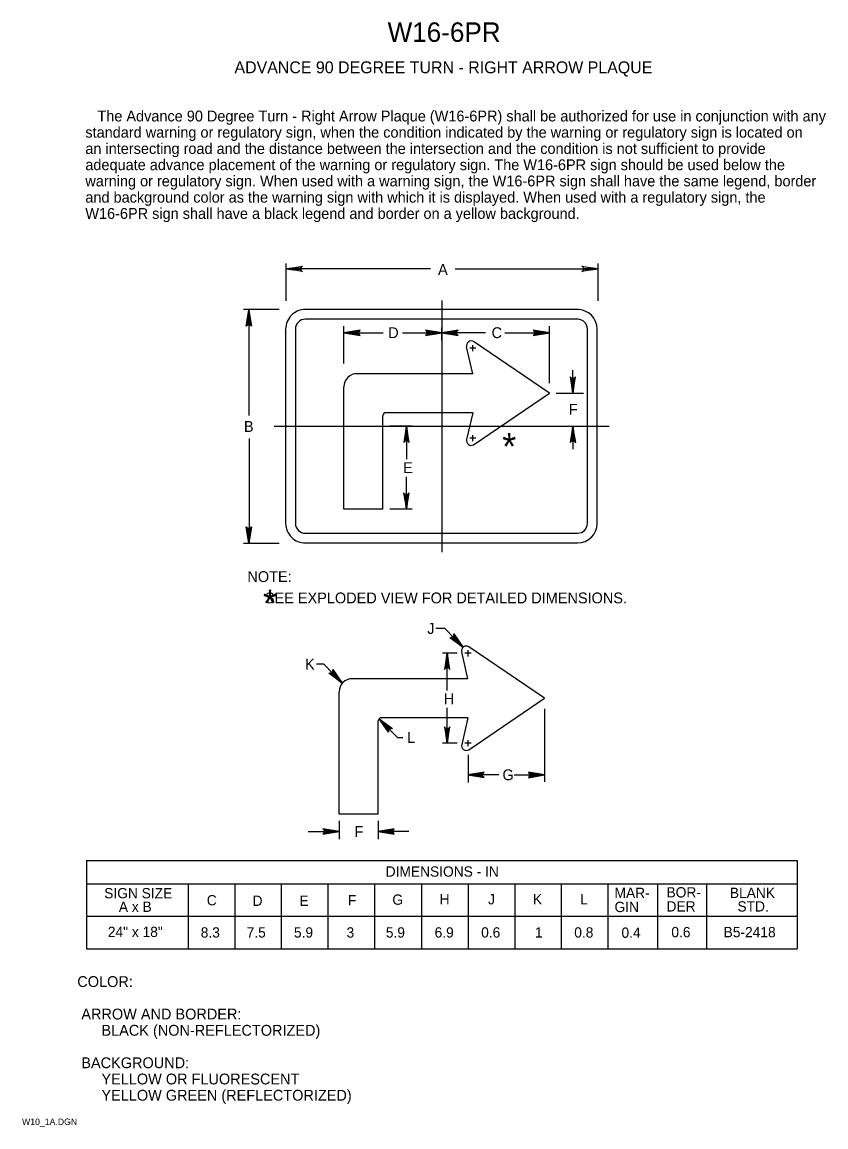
# Model space of a CAD drawing. Extents: x 0.013 to 0.198, y 0.004 to 0.259.
import ezdxf

# ---------------------------------------------------------------- set-up
doc = ezdxf.new("R2010")
doc.units = 0
for name, color, linetype in [('1', 7, 'Continuous'), ('2', 7, 'Continuous'), ('3', 7, 'Continuous')]:
    doc.layers.add(name, color=color, linetype=linetype)

# ---------------------------------------------------------------- blocks, each defined once
blk = doc.blocks.new('RARROW')
at = {"layer": '3'}
for p, q in [((-2.156, 0.28500000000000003), (-2.2665, 0.384625)), ((-2.2665, 0.384625), (0, 0)), ((0, 0), (-2.2665, -0.379125)), ((-2.156, 0.28500000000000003), (-2.075625, 0.12075)), ((0, 0), (-2.156, 0.28500000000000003)), ((-2.14975, -0.2705), (0, 0)), ((-2.075625, 0.12075), (0, 0)), ((0, 0), (-2.074, -0.108)), ((-2.2665, -0.379125), (-2.14975, -0.2705)), ((-2.074, -0.108), (-2.14975, -0.2705))]:
    blk.add_line(p, q, dxfattribs=at)

msp = doc.modelspace()

# ---------------------------------------------------------------- linework, layer by layer
at = {"layer": '1'}
for p, q in [((0.10950949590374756, 0.19475368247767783), (0.10950949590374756, 0.13669624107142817)), ((0.11666823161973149, 0.17787309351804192), (0.08993050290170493, 0.17787309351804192)), ((0.1166682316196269, 0.16887309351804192), (0.09667553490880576, 0.16887309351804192)), ((0.07079216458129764, 0.16574452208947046), (0.14811133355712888, 0.16574452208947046)), ((0.09593050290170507, 0.1466010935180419), (0.08693050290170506, 0.14660109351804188)), ((0.11554471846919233, 0.10743259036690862), (0.08880698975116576, 0.10743259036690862)), ((0.11554471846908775, 0.09843259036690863), (0.09555202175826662, 0.09843259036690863)), ((0.09480698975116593, 0.07616059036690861), (0.08580698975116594, 0.07616059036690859))]:
    msp.add_line(p, q, dxfattribs=at)
for centre, radius, start, end in [((0.08993050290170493, 0.1748730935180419), 0.0029999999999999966, 89.50813388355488, 180), ((0.09668050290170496, 0.16812309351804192), 0.0007499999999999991, 90.19273955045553, 90.19273955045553), ((0.09668050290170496, 0.16812309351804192), 0.0007499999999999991, 90.3795294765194, 179.99999999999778), ((0.09668050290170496, 0.16812309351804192), 0.0007499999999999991, 90.25516062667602, 90.25565038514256), ((0.08880698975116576, 0.1044325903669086), 0.0029999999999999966, 89.50813388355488, 180), ((0.09555698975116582, 0.09768259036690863), 0.0007499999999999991, 90.19273955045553, 90.19273955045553), ((0.09555698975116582, 0.09768259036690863), 0.0007499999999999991, 90.3795294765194, 179.99999999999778), ((0.09555698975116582, 0.09768259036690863), 0.0007499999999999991, 90.25516062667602, 90.25565038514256)]:
    msp.add_arc(centre, radius, start, end, dxfattribs=at)
at = {"layer": '3'}
for p, q in [((0.07359843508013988, 0.1946907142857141), (0.07359843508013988, 0.20331284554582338)), ((0.10689328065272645, 0.20206284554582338), (0.07363359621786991, 0.20206284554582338)), ((0.1125947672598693, 0.20206284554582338), (0.1455984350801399, 0.20206284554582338)), ((0.1455984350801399, 0.1946907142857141), (0.1455984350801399, 0.20331284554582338)), ((0.07196701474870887, 0.19268784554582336), (0.0637585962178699, 0.19268784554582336)), ((0.0650085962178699, 0.1682504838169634), (0.0650085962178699, 0.19268784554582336)), ((0.14105197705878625, 0.1926907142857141), (0.07796701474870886, 0.1926907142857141)), ((0.14099731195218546, 0.1904407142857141), (0.07796701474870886, 0.1904407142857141)), ((0.08693050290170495, 0.18023608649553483), (0.08693050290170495, 0.1888582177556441)), ((0.13436436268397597, 0.1756636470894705), (0.13436436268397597, 0.1888582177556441)), ((0.07346701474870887, 0.1881907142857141), (0.07346701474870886, 0.14329059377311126)), ((0.07571701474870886, 0.1881907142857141), (0.07571701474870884, 0.14329059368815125)), ((0.08693050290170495, 0.18730692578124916), (0.09596335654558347, 0.18730692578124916)), ((0.10046977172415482, 0.18730692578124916), (0.109505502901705, 0.18730692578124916)), ((0.11961581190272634, 0.18730692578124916), (0.109505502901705, 0.18730692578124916)), ((0.10950749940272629, 0.1855104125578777), (0.10950749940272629, 0.18854687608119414)), ((0.12402263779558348, 0.18730692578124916), (0.13436436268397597, 0.18730692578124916)), ((0.14311543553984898, 0.14329446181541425), (0.14311543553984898, 0.18819458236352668)), ((0.14536543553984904, 0.14329446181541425), (0.145365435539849, 0.18819458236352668)), ((0.11666823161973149, 0.17787309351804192), (0.11523606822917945, 0.1840800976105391)), ((0.11668104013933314, 0.18376059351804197), (0.11596392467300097, 0.18376059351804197)), ((0.11668104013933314, 0.18376059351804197), (0.11668104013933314, 0.1844777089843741)), ((0.11668104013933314, 0.18304347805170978), (0.11668104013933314, 0.18376059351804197)), ((0.1173981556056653, 0.18376059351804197), (0.11668104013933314, 0.18376059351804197)), ((0.13436436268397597, 0.17337309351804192), (0.11685011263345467, 0.1852776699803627)), ((0.13975559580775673, 0.17340306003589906), (0.13975559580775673, 0.17872373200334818)), ((0.08693050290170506, 0.14660109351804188), (0.08693050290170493, 0.1748730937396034)), ((0.11684707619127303, 0.16145791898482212), (0.13436436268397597, 0.17337309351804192)), ((0.13592554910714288, 0.17337309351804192), (0.14222058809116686, 0.17337309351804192)), ((0.1166682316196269, 0.16887309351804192), (0.11523606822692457, 0.16266608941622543)), ((0.09593050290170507, 0.1466010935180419), (0.09593050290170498, 0.16812309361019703)), ((0.10265277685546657, 0.16574452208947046), (0.0974990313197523, 0.16574452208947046)), ((0.10135723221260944, 0.1657383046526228), (0.10135723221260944, 0.1581697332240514)), ((0.11668104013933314, 0.16298559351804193), (0.11668104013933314, 0.1637027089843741)), ((0.13592554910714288, 0.16574678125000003), (0.14222058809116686, 0.16574678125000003)), ((0.1397789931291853, 0.1657383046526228), (0.1397789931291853, 0.16044909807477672)), ((0.0650085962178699, 0.1629473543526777), (0.0650085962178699, 0.13885684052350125)), ((0.11668104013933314, 0.16298559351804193), (0.11596392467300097, 0.16298559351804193)), ((0.11668104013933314, 0.1622684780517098), (0.11668104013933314, 0.16298559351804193)), ((0.1173981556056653, 0.16298559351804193), (0.11668104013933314, 0.16298559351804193)), ((0.10133383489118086, 0.1466010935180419), (0.10133383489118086, 0.15407830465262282)), ((0.102629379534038, 0.1466010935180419), (0.09747563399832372, 0.1466010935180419)), ((0.07796701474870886, 0.1410405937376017), (0.14086543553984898, 0.1410405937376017)), ((0.07196701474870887, 0.13868784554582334), (0.0637585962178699, 0.13868784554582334)), ((0.07796701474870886, 0.1387905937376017), (0.14086543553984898, 0.1387905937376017)), ((0.11018019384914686, 0.11901097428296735), (0.10811614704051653, 0.11901097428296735)), ((0.11443908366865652, 0.1146778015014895), (0.11018019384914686, 0.11901097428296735)), ((0.13324084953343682, 0.10293259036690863), (0.11572659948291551, 0.11483716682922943)), ((0.11308116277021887, 0.11332009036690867), (0.10963910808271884, 0.11332009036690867)), ((0.11076471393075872, 0.10473138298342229), (0.11076471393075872, 0.11251084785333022)), ((0.11554471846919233, 0.10743259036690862), (0.11411255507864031, 0.11363959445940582)), ((0.115557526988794, 0.11332009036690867), (0.11484041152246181, 0.11332009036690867)), ((0.115557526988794, 0.11332009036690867), (0.115557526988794, 0.11403720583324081)), ((0.11627464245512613, 0.11332009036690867), (0.115557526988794, 0.11332009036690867)), ((0.115557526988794, 0.11260297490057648), (0.115557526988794, 0.11332009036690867)), ((0.08228011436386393, 0.11078240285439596), (0.08060757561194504, 0.11078240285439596)), ((0.08653900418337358, 0.1064492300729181), (0.08228011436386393, 0.11078240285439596)), ((0.08580698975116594, 0.07616059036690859), (0.08580698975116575, 0.10443259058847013)), ((0.11572356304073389, 0.09101741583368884), (0.13324084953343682, 0.10293259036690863)), ((0.11076471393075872, 0.0925565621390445), (0.11076471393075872, 0.10068566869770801)), ((0.13324084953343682, 0.10050852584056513), (0.13324084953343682, 0.08358852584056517)), ((0.09480698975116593, 0.07616059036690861), (0.09480698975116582, 0.09768259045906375)), ((0.09501900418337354, 0.09819780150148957), (0.09927789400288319, 0.09386462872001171)), ((0.11554471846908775, 0.09843259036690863), (0.11411255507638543, 0.09222558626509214)), ((0.09927789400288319, 0.09386462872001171), (0.10051614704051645, 0.09386462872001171)), ((0.11308194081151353, 0.09254509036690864), (0.10963988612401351, 0.09254509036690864)), ((0.115557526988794, 0.09254509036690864), (0.11484041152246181, 0.09254509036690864)), ((0.115557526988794, 0.09254509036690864), (0.115557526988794, 0.09326220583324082)), ((0.115557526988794, 0.09182797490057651), (0.115557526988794, 0.09254509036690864)), ((0.11627464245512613, 0.09254509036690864), (0.115557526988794, 0.09254509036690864)), ((0.115557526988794, 0.08985138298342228), (0.115557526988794, 0.0834513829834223)), ((0.12266765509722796, 0.08521709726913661), (0.11552765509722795, 0.08521709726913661)), ((0.12622194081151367, 0.08521709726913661), (0.13324084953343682, 0.08521709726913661)), ((0.08580698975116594, 0.07465494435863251), (0.08580698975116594, 0.07041494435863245)), ((0.09480698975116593, 0.07465494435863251), (0.09480698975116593, 0.07041494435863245)), ((0.07866698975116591, 0.07218065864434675), (0.08580698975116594, 0.07218065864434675)), ((0.10193043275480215, 0.07218065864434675), (0.09479043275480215, 0.07218065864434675)), ((0.027461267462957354, 0.0654753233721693), (0.19155772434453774, 0.0654753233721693)), ((0.027461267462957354, 0.0654753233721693), (0.027461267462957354, 0.04510032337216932)), ((0.19155772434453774, 0.06547532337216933), (0.19155772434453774, 0.04510032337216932)), ((0.027461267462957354, 0.06010032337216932), (0.19155772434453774, 0.06010032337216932)), ((0.05096126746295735, 0.06010032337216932), (0.05096126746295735, 0.04510032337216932)), ((0.06171126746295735, 0.06010032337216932), (0.06171126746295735, 0.04510032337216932)), ((0.07246126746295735, 0.06010032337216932), (0.07246126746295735, 0.04510032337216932)), ((0.08321126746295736, 0.06010032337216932), (0.08321126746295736, 0.04510032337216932)), ((0.09396126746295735, 0.06010032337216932), (0.09396126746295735, 0.04510032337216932)), ((0.10483626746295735, 0.06010032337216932), (0.10483626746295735, 0.04510032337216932)), ((0.11558626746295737, 0.06010032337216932), (0.11558626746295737, 0.04510032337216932)), ((0.12633626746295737, 0.06010032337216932), (0.12633626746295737, 0.04510032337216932)), ((0.13708626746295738, 0.06010032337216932), (0.13708626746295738, 0.04510032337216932)), ((0.1478362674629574, 0.06010032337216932), (0.1478362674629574, 0.04510032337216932)), ((0.1592891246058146, 0.06010032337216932), (0.1592891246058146, 0.04510032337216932)), ((0.17062169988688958, 0.06010032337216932), (0.17062169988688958, 0.04510032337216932)), ((0.027461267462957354, 0.05260032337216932), (0.19155772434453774, 0.05260032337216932)), ((0.027461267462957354, 0.04510032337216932), (0.19155772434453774, 0.04510032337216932))]:
    msp.add_line(p, q, dxfattribs=at)
for centre, radius, start, end in [((0.07799927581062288, 0.1881623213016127), 0.004532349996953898, 89.64106666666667, 179.6410666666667), ((0.14086543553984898, 0.18819458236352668), 0.0045000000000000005, 0, 90), ((0.07799927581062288, 0.1881623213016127), 0.0022824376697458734, 89.28723611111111, 179.2872361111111), ((0.14086543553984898, 0.18819458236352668), 0.0022500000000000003, 0, 90), ((0.11629692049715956, 0.18433678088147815), 0.0010914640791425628, 59.54676398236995, 193.60184176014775), ((0.11629692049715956, 0.16240940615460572), 0.0010914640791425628, 166.39815823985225, 300.45323601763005), ((0.07799540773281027, 0.1433228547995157), 0.004528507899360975, 180.4081777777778, 270.40817777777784), ((0.07799540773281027, 0.1433228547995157), 0.002278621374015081, 180.81123055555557, 270.81123055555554), ((0.14086543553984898, 0.14329446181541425), 0.0045000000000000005, 270, 0), ((0.14086543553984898, 0.14329446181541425), 0.0022500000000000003, 270, 0), ((0.11517340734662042, 0.11389627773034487), 0.0010914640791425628, 59.54676398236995, 193.60184176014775), ((0.11517340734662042, 0.09196890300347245), 0.0010914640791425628, 166.39815823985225, 300.45323601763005)]:
    msp.add_arc(centre, radius, start, end, dxfattribs=at)

# ---------------------------------------------------------------- block references
for p, xscale, yscale, rotation in [((0.07359201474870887, 0.2020657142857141), 0.0016545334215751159, 0.0016366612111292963, 180), ((0.06496701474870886, 0.19256571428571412), 0.0016545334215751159, 0.0016366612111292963, 90), ((0.08693050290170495, 0.18730692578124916), 0.0016545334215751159, -0.0016366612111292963, 180), ((0.109505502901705, 0.18730692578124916), 0.0016545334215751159, -0.0016366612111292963, 180), ((0.13975559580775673, 0.17340306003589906), 0.0016545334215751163, -0.0016366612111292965, -89.99999999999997), ((0.10135723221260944, 0.1657383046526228), 0.0016545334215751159, -0.0016366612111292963, 90.00000000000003), ((0.1397789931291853, 0.1657383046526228), 0.0016545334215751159, -0.0016366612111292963, 90.00000000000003), ((0.10133383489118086, 0.1466010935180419), 0.0016545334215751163, -0.0016366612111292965, -89.99999999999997), ((0.06496701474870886, 0.13873470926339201), 0.0016545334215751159, 0.0016366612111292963, -90), ((0.11443908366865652, 0.1146778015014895), 0.0016545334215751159, 0.0016366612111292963, -45.49534021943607), ((0.11075051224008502, 0.11334852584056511), 0.0016545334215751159, -0.0016366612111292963, 90.00000000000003), ((0.08653900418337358, 0.1064492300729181), 0.0016545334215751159, 0.0016366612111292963, -45.49534021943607), ((0.09501900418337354, 0.09819780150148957), 0.0016545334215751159, 0.0016366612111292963, 134.5046597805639), ((0.11076471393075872, 0.0925565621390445), 0.0016545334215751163, -0.0016366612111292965, -89.99999999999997), ((0.11552765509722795, 0.08521709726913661), 0.0016545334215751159, -0.0016366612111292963, 180), ((0.09479043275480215, 0.07218065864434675), 0.0016545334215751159, -0.0016366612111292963, 180)]:
    msp.add_blockref('RARROW', p, dxfattribs=dict(at, xscale=xscale, yscale=yscale, rotation=rotation))
at = {"layer": '3', "xscale": 0.0016545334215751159}
for p, yscale in [((0.1455984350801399, 0.20206284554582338), 0.0016366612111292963), ((0.109505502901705, 0.18730692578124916), -0.0016366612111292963), ((0.13436436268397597, 0.18730692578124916), -0.0016366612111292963), ((0.13324084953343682, 0.08521709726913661), -0.0016366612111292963), ((0.08580698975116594, 0.07218065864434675), -0.0016366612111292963)]:
    msp.add_blockref('RARROW', p, dxfattribs=dict(at, yscale=yscale))

# ---------------------------------------------------------------- texts
at = {"layer": '1'}
for s, height, p in [('W16-6PR', 0.0045000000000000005, (0.09699590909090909, 0.2545)), ('ADVANCE 90 DEGREE TURN - RIGHT ARROW PLAQUE', 0.00275025, (0.06165046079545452, 0.24725)), ('*', 0.006220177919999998, (0.12344607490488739, 0.15797148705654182)), ('*', 0.006220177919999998, (0.068223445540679, 0.12174596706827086)), ('COLOR:', 0.0024997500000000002, (0.025375, 0.036249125)), (' ARROW AND BORDER:', 0.0024997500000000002, (0.025375, 0.028749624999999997)), ('      BLACK (NON-REFLECTORIZED)', 0.0024997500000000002, (0.025375, 0.024999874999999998)), (' BACKGROUND:', 0.0024997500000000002, (0.025375, 0.017500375)), ('      YELLOW OR FLUORESCENT ', 0.0024997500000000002, (0.025375, 0.013750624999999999)), ('      YELLOW GREEN (REFLECTORIZED)', 0.0024997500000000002, (0.025375, 0.010000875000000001)), ('W10_1A.DGN', 0.0015, (0.012625, 0.004375))]:
    msp.add_text(s, height=height, dxfattribs=at).set_placement(p)
at = {"layer": '2'}
for s, p in [('   The Advance 90 Degree Turn - Right Arrow Plaque (W16-6PR) shall be authorized for use in conjunction with any ', (0.027230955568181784, 0.23612525)), ('standard warning or regulatory sign, when the condition indicated by the warning or regulatory sign is located on ', (0.027230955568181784, 0.23237549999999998)), ('an intersecting road and the distance between the intersection and the condition is not sufficient to provide ', (0.027230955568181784, 0.22862575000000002)), ('adequate advance placement of the warning or regulatory sign. The W16-6PR sign should be used below the ', (0.027230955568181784, 0.22487600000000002)), ('warning or regulatory sign. When used with a warning sign, the W16-6PR sign shall have the same legend, border ', (0.027230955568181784, 0.22112625)), ('and background color as the warning sign with which it is displayed. When used with a regulatory sign, the ', (0.027230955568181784, 0.2173765)), ('W16-6PR sign shall have a black legend and border on a yellow background.', (0.027230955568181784, 0.21362675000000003))]:
    msp.add_text(s, height=0.0024997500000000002, dxfattribs=at).set_placement(p)
at = {"layer": '3'}
for s, height, p in [('A', 0.0024997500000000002, (0.10864247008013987, 0.2006907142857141)), ('D', 0.0024997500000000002, (0.09713705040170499, 0.18609318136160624)), ('C', 0.0024997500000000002, (0.12099814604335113, 0.18609318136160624)), ('B', 0.0024997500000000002, (0.06384201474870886, 0.16443797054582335)), ('E', 0.0024997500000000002, (0.10058327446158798, 0.15492293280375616)), ('NOTE:', 0.0024997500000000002, (0.06463573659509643, 0.1297688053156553)), ('   SEE EXPLODED VIEW FOR DETAILED DIMENSIONS.', 0.0024997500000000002, (0.06588351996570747, 0.12484576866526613)), ('J', 0.0024997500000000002, (0.10615758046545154, 0.1177780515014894)), ('K', 0.0024997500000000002, (0.07792572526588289, 0.10954948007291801)), ('H', 0.0024997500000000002, (0.10996763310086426, 0.10155780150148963)), ('L', 0.0024997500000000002, (0.10151049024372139, 0.09259780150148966)), ('G', 0.0024997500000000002, (0.12351297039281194, 0.08400335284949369)), ('F', 0.0024997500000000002, (0.08935103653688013, 0.07090281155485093)), ('DIMENSIONS - IN', 0.0023752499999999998, (0.09655178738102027, 0.06172532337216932)), ('SIGN SIZE', 0.0023752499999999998, (0.031586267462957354, 0.056725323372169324)), ('MAR-', 0.0023752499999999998, (0.14937191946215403, 0.05679995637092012)), ('BOR-', 0.0023752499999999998, (0.16137191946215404, 0.05692495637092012)), ('BLANK', 0.0023752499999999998, (0.1759969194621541, 0.05679995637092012)), ('C', 0.0023752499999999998, (0.05526438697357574, 0.05510032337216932)), ('D', 0.0023752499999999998, (0.06583626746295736, 0.05497532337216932)), ('E', 0.0023752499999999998, (0.07665626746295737, 0.05497532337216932)), ('F', 0.0023752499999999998, (0.08783626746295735, 0.05510032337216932)), ('G', 0.0023752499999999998, (0.09809912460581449, 0.05523883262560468)), ('H', 0.0023752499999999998, (0.10901438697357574, 0.055328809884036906)), ('J', 0.0023752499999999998, (0.12018977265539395, 0.055328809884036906)), ('K', 0.0023752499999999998, (0.1305323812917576, 0.055328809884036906)), ('L', 0.0023752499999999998, (0.14143713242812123, 0.055328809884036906)), ('A x B', 0.0023752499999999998, (0.03496126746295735, 0.05360032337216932)), ('GIN', 0.0023752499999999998, (0.14937191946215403, 0.053549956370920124)), ('DER', 0.0023752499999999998, (0.16137191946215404, 0.053674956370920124)), ('STD.', 0.0023752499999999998, (0.1777469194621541, 0.053674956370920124)), ('24" x 18"', 0.0023752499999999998, (0.03242261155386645, 0.04778769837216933)), ('8.3', 0.0023752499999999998, (0.05386432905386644, 0.047662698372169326)), ('7.5', 0.0023752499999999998, (0.06445765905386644, 0.047662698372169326)), ('5.9', 0.0023752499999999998, (0.07538052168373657, 0.047662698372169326)), ('3', 0.0023752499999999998, (0.08751788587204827, 0.047662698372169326)), ('5.9', 0.0023752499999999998, (0.09658337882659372, 0.047662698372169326)), ('6.9', 0.0023752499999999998, (0.10784695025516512, 0.047662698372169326)), ('0.6', 0.0023752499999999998, (0.1185933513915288, 0.047662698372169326)), ('1', 0.0023752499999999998, (0.13099379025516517, 0.047662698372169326)), ('0.8', 0.0023752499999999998, (0.1400803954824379, 0.047662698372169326)), ('0.4', 0.0023752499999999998, (0.1509789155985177, 0.04761233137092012)), ('0.6', 0.0023752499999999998, (0.16249043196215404, 0.04773733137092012)), ('B5-2418', 0.0023752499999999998, (0.17455728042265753, 0.04773733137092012))]:
    msp.add_text(s, height=height, dxfattribs=at).set_placement(p)
msp.add_text('F', height=0.0024997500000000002, rotation=360, dxfattribs=at).set_placement((0.13883289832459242, 0.16839549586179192))

doc.saveas('drawing.dxf')
